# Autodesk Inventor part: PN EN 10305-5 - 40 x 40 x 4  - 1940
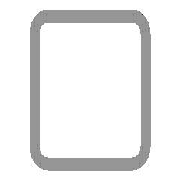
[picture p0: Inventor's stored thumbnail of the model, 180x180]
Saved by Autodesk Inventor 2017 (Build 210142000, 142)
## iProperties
Created: 2016-02
Part Number: PN EN 10305-5 - 40 x 40 x 4  - 1940
Material: Stal, miękka
Description: Rury stalowe do zastosowań precyzyjnych -  (Część 5: Rury kwadratowe, spawane, wymiarowane na zimno)
Document SubType Name: Modeling
Standard: PN
Designer: WindowsX
Standards Organization: PN
Language: pl-PL
Size Designation: 40 x 40 x 4
Categories: <MemberInstance><Categories><Category DisplayName="Kształtowniki konstrukcyjne" InternalName="089c4875-fa83-4c05-b084-43b9cc11f5ed" Mnemonic="GRDR"><CategoryPar
Stock Number: 40 x 40 x 4
Density: 7.85 g/cm^3
Appearance: Częściowo polerowana
_CCFamilyMember: 29
_CCFamilyDisplayName: PN EN 10305-5 (Rury kwadratowe, spawane, wymiarowane na zimno) - Rury stalowe do zastosowań precyzyjnych -  (Część 5: Rury kwadratowe, spawane, wymiarowane na z
_FrameMemberDoc: Frame Member File
_Version: 15.0.0
_GetPNFromCC: 1
G_W: 40,000 mm
G_H: 40,000 mm
G_L: 1940,000 mm
IsCustomPart: 1
Author: WindowsX
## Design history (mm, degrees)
node "Płaszczyzna początkowa"
node "Płaszczyzna końcowa"
sketch "Szkic"
  geometry: L1 (-20, -11.2)-(-20, 11.2); L2 (-11.2, 20)-(11.2, 20); L3 (20, 11.2)-(20, -11.2); L4 (11.2, -20)-(-11.2, -20); L5 (-11.2, 16)-(11.2, 16); L6 (16, 11.2)-(16, -11.2); L7 (11.2, -16)-(-11.2, -16); L8 (-16, -11.2)-(-16, 11.2); L9 (0, 30.552)-(0, -30.552) reference; L10 (-30.552, 0)-(30.552, 0) reference; A1 r 8.8 centre (-11.2, -11.2) between (-20, -11.2) and (-11.2, -20); A2 r 8.8 centre (-11.2, 11.2) between (-11.2, 20) and (-20, 11.2); A3 r 8.8 centre (11.2, 11.2) between (20, 11.2) and (11.2, 20); A4 r 8.8 centre (11.2, -11.2) between (11.2, -20) and (20, -11.2); A5 r 4.8 centre (-11.2, 11.2) between (-11.2, 16) and (-16, 11.2); A6 r 4.8 centre (11.2, 11.2) between (16, 11.2) and (11.2, 16); A7 r 4.8 centre (11.2, -11.2) between (11.2, -16) and (16, -11.2); A8 r 4.8 centre (-11.2, -11.2) between (-16, -11.2) and (-11.2, -16)
  constraints: 16 end point, 16 point on circle, 8 centre point, 8 tangent, 4 parallel, 3 equal radius, 2 perpendicular, 7 other
  dimensions: "d7" = 8.8 radius of A1 (= G_IR); "d10" = 40 distance between parallel lines of L2 L4 (= G_H); "d11" = 40 distance between parallel lines of L1 L3 (= G_W); "d12" = 4 distance between parallel lines of L3 L6 (= G_T); "d15" = 20 distance between parallel lines of L2 L10 (= 0.5 x d10); "d16" = 20 distance between parallel lines of L9 L3 (= 0.5 x d11)
extrude "Bryła" new body sketch "Szkic" stored distance "d3" = 1940 (= G_L); taper "d4" = 0 deg
node "Driven Length"
  sketch "Sketch3"
    geometry: L1 (0, 0)-(10, 0) reference
    constraints: 2 end point, 1 horizontal
  workplane "Work Plane3"
  sketch "Sketch4"
    geometry: L1 (-2, 0)-(12, 0) reference; L2 (-2, 1940)-(12, 1940) reference
    dimensions: "d18" = 1940 distance between parallel lines of L1 L2 (derived)
body "Solid1"
other parameters: "G_W" = 40 [user parameter; used in 1 equation term], "G_H" = 40 [user parameter; used in 1 equation term], "G_T" = 4 [user parameter; used in 1 equation term], "G_IR" = 8.8 [user parameter; used in 1 equation term], "G_L" = 1940 (= d18) [user parameter; used in 1 equation term], "G_OFFSET_START" = 0 [user parameter; used in 1 equation term], "G_OFFSET_END" = 0 [user parameter; used in 1 equation term], "d13" = 0 (computed from G_OFFSET_START), "d17" = 90 deg
